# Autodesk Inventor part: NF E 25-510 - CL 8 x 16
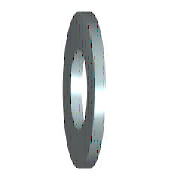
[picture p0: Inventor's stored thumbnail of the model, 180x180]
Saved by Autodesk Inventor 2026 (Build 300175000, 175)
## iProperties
IsCustomPart: 0
Created: 2025-01
Part Number: NF E 25-510 - CL 8 x 16
Material: Acier, doux
Description: Rondelles cuvette
Document SubType Name: Modeling
Standard: NF E 25-510
Designer: thierry.jost
Standards Organization: AFNOR
Language: fr-FR
Size Designation: CL 8 x 16
Categories: <MemberInstance><Categories><Category DisplayName="Visserie" InternalName="e4da775c-781d-43d5-af7c-5136215cf5a6" Mnemonic="FSTN"><Category DisplayName="Rondelle
Density: 7.85 g/cm^3
Appearance: Semi-poli
Author: thierry.jost
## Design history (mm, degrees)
body "Solid1"
sketch "Esquisse"
  geometry: C1 r 8 at (0, 0); C2 r 4.2 at (0, 0); 1 further point
  constraints: 2 centre point, 2 coincident
  dimensions: "d0" = 8.4 diameter of C2 (= SD1); "d1" = 16 diameter of C1 (= SD2)
extrude "Corps" new body sketch "Esquisse" distance "d2" = 1.9 (= SD); taper "d3" = 0 deg
workaxis "Work Axis1"
workplane "Work Plane1"
other parameters: "SD1" = 8.4 [user parameter; used in 1 equation term], "SD2" = 16 [user parameter; used in 1 equation term], "SD" = 1.9 [user parameter; used in 1 equation term], "d4" = 0, "d5" = 0, "d6" = 0, "d7" = 0, "NND" = 8 [user parameter]
